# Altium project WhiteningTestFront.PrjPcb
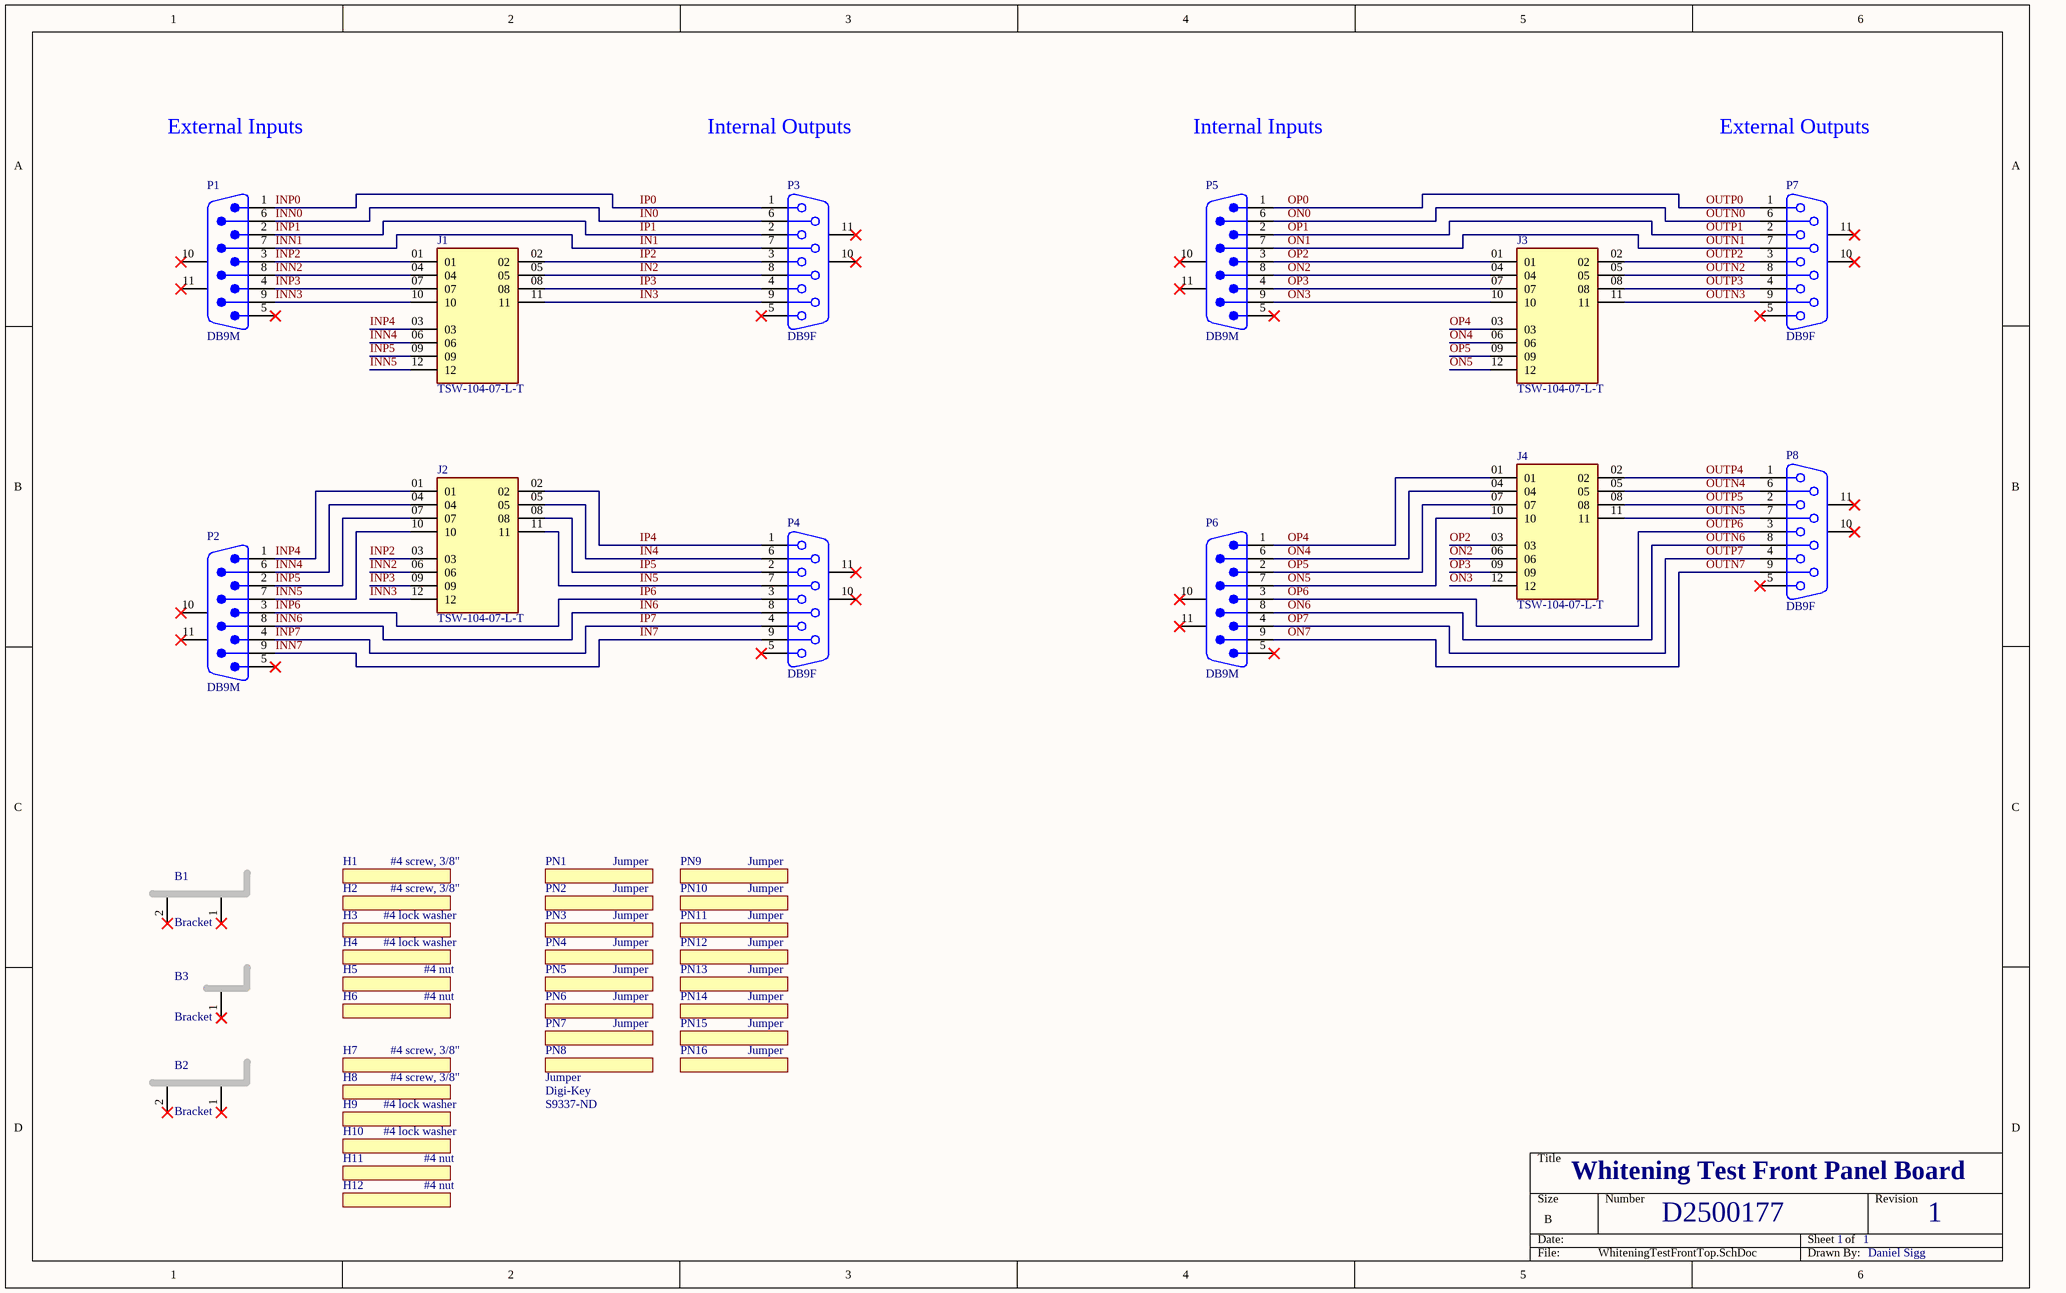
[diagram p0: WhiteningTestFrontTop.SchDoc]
REV: 1; DCC: D2500177
1 sheet, 43 parts. Net scope: global (net labels, ports and power ports of the same name join across sheets).
Board file: WhiteningTestFront.PcbDoc

## Sheet WhiteningTestFrontTop.SchDoc
size B; DocumentNumber: D2500177; Revision: 1; SheetNumber: 1; SheetTotal: 1

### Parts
B1  Bracket  [Bracket-RA_708]
B2  Bracket  [Bracket-RA_708]
B3  Bracket  [Bracket-RA_634]
H1  #4 screw, 3/8"  (mechanical)
H2  #4 screw, 3/8"  (mechanical)
H3  #4 lock washer  (mechanical)
H4  #4 lock washer  (mechanical)
H5  #4 nut  (mechanical)
H6  #4 nut  (mechanical)
H7  #4 screw, 3/8"  (mechanical)
H8  #4 screw, 3/8"  (mechanical)
H9  #4 lock washer  (mechanical)
H10  #4 lock washer  (mechanical)
H11  #4 nut  (mechanical)
H12  #4 nut  (mechanical)
J1  TSW-104-07-L-T  [SAMTEC_TSW-104-07-L-T]
J2  TSW-104-07-L-T  [SAMTEC_TSW-104-07-L-T]
J3  TSW-104-07-L-T  [SAMTEC_TSW-104-07-L-T]
J4  TSW-104-07-L-T  [SAMTEC_TSW-104-07-L-T]
P1  DB9M  [DB9M-RA]
P2  DB9M  [DB9M-RA]
P3  DB9F  [DB9F-ST]
P4  DB9F  [DB9F-ST]
P5  DB9M  [DB9M-RA]
P6  DB9M  [DB9M-RA]
P7  DB9F  [DB9F-RA]
P8  DB9F  [DB9F-RA]
PN1  Jumper  (mechanical)
PN2  Jumper  (mechanical)
PN3  Jumper  (mechanical)
PN4  Jumper  (mechanical)
PN5  Jumper  (mechanical)
PN6  Jumper  (mechanical)
PN7  Jumper  (mechanical)
PN8  Jumper  Part Number: S9337-ND  Distributor: Digi-Key  (mechanical)
PN9  Jumper  (mechanical)
PN10  Jumper  (mechanical)
PN11  Jumper  (mechanical)
PN12  Jumper  (mechanical)
PN13  Jumper  (mechanical)
PN14  Jumper  (mechanical)
PN15  Jumper  (mechanical)
PN16  Jumper  (mechanical)

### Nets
IN0: P1.6 P3.6  [also labelled INN0]
IN1: P1.7 P3.7  [also labelled INN1]
IN2: J1.05 P3.8
IN3: J1.11 P3.9
IN4: J2.05 P4.6
IN5: J2.11 P4.7
IN6: P2.8 P4.8  [also labelled INN6]
IN7: P2.9 P4.9  [also labelled INN7]
INN2: J1.04 J2.06 P1.8
INN3: J1.10 J2.12 P1.9
INN4: J1.06 J2.04 P2.6
INN5: J1.12 J2.10 P2.7
INP0: P1.1 P3.1  [also labelled IP0]
INP1: P1.2 P3.2  [also labelled IP1]
INP2: J1.01 J2.03 P1.3
INP3: J1.07 J2.09 P1.4
INP4: J1.03 J2.01 P2.1
INP5: J1.09 J2.07 P2.2
INP6: P2.3 P4.3  [also labelled IP6]
INP7: P2.4 P4.4  [also labelled IP7]
IP2: J1.02 P3.3
IP3: J1.08 P3.4
IP4: J2.02 P4.1
IP5: J2.08 P4.2
ON0: P5.6 P7.6  [also labelled OUTN0]
ON1: P5.7 P7.7  [also labelled OUTN1]
ON2: J3.04 J4.06 P5.8
ON3: J3.10 J4.12 P5.9
ON4: J3.06 J4.04 P6.6
ON5: J3.12 J4.10 P6.7
ON6: P6.8 P8.8  [also labelled OUTN6]
ON7: P6.9 P8.9  [also labelled OUTN7]
OP0: P5.1 P7.1  [also labelled OUTP0]
OP1: P5.2 P7.2  [also labelled OUTP1]
OP2: J3.01 J4.03 P5.3
OP3: J3.07 J4.09 P5.4
OP4: J3.03 J4.01 P6.1
OP5: J3.09 J4.07 P6.2
OP6: P6.3 P8.3  [also labelled OUTP6]
OP7: P6.4 P8.4  [also labelled OUTP7]
OUTN2: J3.05 P7.8
OUTN3: J3.11 P7.9
OUTN4: J4.05 P8.6
OUTN5: J4.11 P8.7
OUTP2: J3.02 P7.3
OUTP3: J3.08 P7.4
OUTP4: J4.02 P8.1
OUTP5: J4.08 P8.2

Not connected (* = marked no-connect by the designer): B1 1(GND)* 2(GND)*; B2 1(GND)* 2(GND)*; B3 1(GND)*; P1 5* 10(MH1)* 11(MH2)*; P2 5* 10(MH1)* 11(MH2)*; P3 5* 10(MH1)* 11(MH2)*; P4 5* 10(MH1)* 11(MH2)*; P5 5* 10(MH1)* 11(MH2)*; P6 5* 10(MH1)* 11(MH2)*; P7 5* 10(MH1)* 11(MH2)*; P8 5* 10(MH1)* 11(MH2)*

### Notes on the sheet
- External Inputs
- Internal Outputs
- Internal Inputs
- External Outputs
- Whitening Test Front Panel Board
- Daniel Sigg

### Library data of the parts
B1 B2 = Bracket_708: Keystone Electronics right-angle 6-32 steel, 708; Part Number: 36-708-ND
B3 = Bracket_634: Keystone Electronics right-angle 6-32 steel, 634; Part Number: 36-634-ND
H1 H2 H7 H8 = Partlist: Mounting hardware; Part Number: 90272A108
H3 H4 H9 H10 = Partlist: Mounting hardware; Part Number: 91113A005
H5 H6 H11 H12 = Partlist: Mounting hardware; Part Number: 90480A005
J1-J4 = TSW-104-07-L-T: Jumper header; Part Number: SAM12310-ND
P1 P2 = DB9M: Plug Assembly, 9 Position, Right Angle, .318 Series; Part Number: 609-4954-ND
P3 P4 = DB9F: Receptacle Assembly, 9 Position, Right Angle, .318 Series; Part Number: 609-5874-ND
P5 P6 = DB9M: Plug Assembly, 9 Position, Right Angle, .318 Series; Part Number: 609-4954-ND; System: Connector
P7 P8 = DB9F: Receptacle Assembly, 9 Position, Right Angle, .318 Series; Part Number: 609-6160-ND
PN1-PN7 PN9-PN16 = Partlist: Part Number: S9337-ND
PN8 = Partlist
